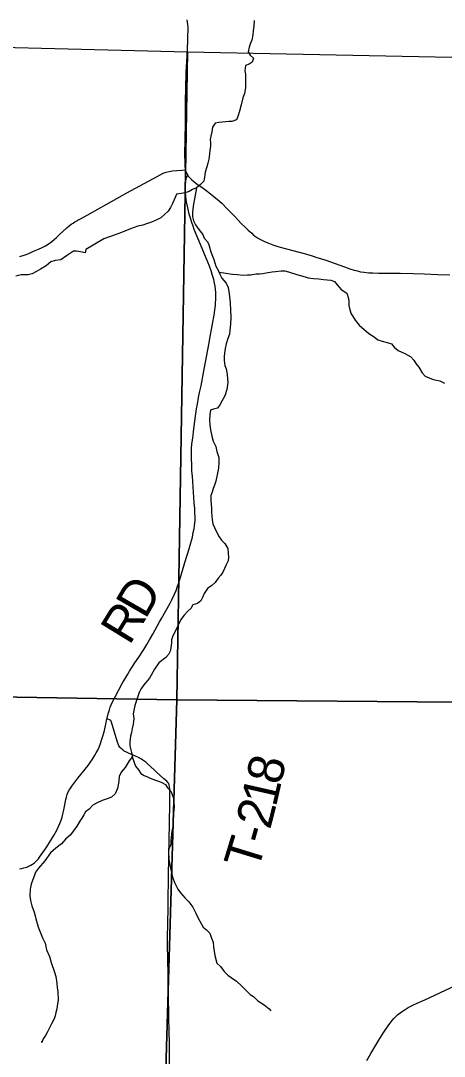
# Model space of a CAD drawing. Extents: x -1.2 to 34, y -8.5 to 22.
# Drawn here: x 7.031 to 7.701, y 15.11 to 16.749 of the extents above; entities that cross this region are included whole.
import ezdxf

# ---------------------------------------------------------------- set-up
doc = ezdxf.new("R2010")
doc.units = 0
for name, color, linetype in [('GM_X_County_Road', 7, 'Continuous'), ('GM_X_Minor_River', 7, 'Continuous'), ('GM_X_Section', 7, 'Continuous'), ('GM_X_Township_Road', 7, 'Continuous'), ('GM_X_Township_Road_Text', 7, 'Continuous')]:
    doc.layers.add(name, color=color, linetype=linetype)

msp = doc.modelspace()

# ---------------------------------------------------------------- linework, layer by layer
at = {"layer": 'GM_X_County_Road'}
for points in [[(7.2935, 16.7497), (7.2943, 16.746), (7.2948, 16.7425), (7.2951, 16.7383), (7.2953, 16.7327), (7.2949, 16.7256), (7.2946, 16.7165), (7.2934, 16.6928), (7.292, 16.6666), (7.2914, 16.6409), (7.2912, 16.6224), (7.291, 16.5891), (7.2905, 16.5581), (7.2902, 16.5394), (7.2905, 16.5216), (7.2907, 16.5172), (7.291, 16.514), (7.2913, 16.5128), (7.2916, 16.5112), (7.2925, 16.5088), (7.2938, 16.5061), (7.2951, 16.504), (7.2956, 16.5031), (7.2963, 16.5022), (7.2978, 16.5004), (7.2989, 16.4992), (7.3012, 16.497), (7.3047, 16.494), (7.3107, 16.4896), (7.3172, 16.4851), (7.3256, 16.4789), (7.3311, 16.4745), (7.3365, 16.4704), (7.3422, 16.4655), (7.3488, 16.4598), (7.3582, 16.4505), (7.3693, 16.4389), (7.3797, 16.4279), (7.3864, 16.4214), (7.3905, 16.4173), (7.3962, 16.4121), (7.3992, 16.4094), (7.4024, 16.4071), (7.4056, 16.4049), (7.4102, 16.4021), (7.4153, 16.3995), (7.4216, 16.3969), (7.4297, 16.394), (7.436, 16.392), (7.4411, 16.3904), (7.4813, 16.3794), (7.4866, 16.3779), (7.492, 16.3763), (7.499, 16.3741), (7.505, 16.3721), (7.5133, 16.3694), (7.5281, 16.3642), (7.5428, 16.3589), (7.5516, 16.3559), (7.5583, 16.3538), (7.5633, 16.3525), (7.5684, 16.3514), (7.574, 16.3505), (7.5811, 16.3498), (7.588, 16.3494), (7.5967, 16.3492), (7.6308, 16.3491), (7.6517, 16.3486), (7.6692, 16.3481), (7.6908, 16.3472), (7.7094, 16.3463)], [(7.5783, 15.1031), (7.5846, 15.1146), (7.5892, 15.1223), (7.5957, 15.1327), (7.6032, 15.1447), (7.6085, 15.153), (7.6149, 15.1619), (7.6185, 15.1666), (7.6211, 15.1696), (7.6241, 15.1727), (7.627, 15.1755), (7.631, 15.1788), (7.6345, 15.1814), (7.6389, 15.1841), (7.6438, 15.187), (7.6512, 15.1908), (7.658, 15.194), (7.6699, 15.1994), (7.7186, 15.2218)]]:
    msp.add_lwpolyline(points, dxfattribs=at)
at = {"layer": 'GM_X_Minor_River'}
for points in [[(7.4, 16.7488), (7.3997, 16.74), (7.3987, 16.7324), (7.398, 16.7259), (7.3963, 16.7179), (7.3941, 16.7129), (7.3923, 16.7064), (7.3905, 16.6991), (7.3936, 16.6938), (7.3989, 16.6893), (7.3971, 16.6828), (7.3923, 16.6797), (7.3862, 16.6777), (7.3852, 16.669), (7.3864, 16.664), (7.3862, 16.6545), (7.3864, 16.6423), (7.3846, 16.6335), (7.3824, 16.6267), (7.3796, 16.6152), (7.3767, 16.6056), (7.3741, 16.5972), (7.3723, 16.5915), (7.3648, 16.5891), (7.3599, 16.589), (7.355, 16.5886), (7.3444, 16.5873), (7.3383, 16.5864), (7.3343, 16.5799), (7.3332, 16.5726), (7.3318, 16.5657), (7.3308, 16.5604), (7.3312, 16.5555), (7.3309, 16.5494), (7.3302, 16.5436), (7.3296, 16.5375), (7.3286, 16.5295), (7.3271, 16.523), (7.3253, 16.5173), (7.3228, 16.5089), (7.3218, 16.5012), (7.3203, 16.4948), (7.3155, 16.4893), (7.3088, 16.4839), (7.3024, 16.4812), (7.2975, 16.4784), (7.2911, 16.4764), (7.2847, 16.4752), (7.2775, 16.4739), (7.2753, 16.469), (7.2709, 16.4594), (7.2679, 16.4532), (7.2639, 16.4471), (7.2523, 16.4366), (7.2474, 16.4339), (7.2376, 16.4296), (7.2297, 16.4272), (7.224, 16.4252), (7.2161, 16.4235), (7.2044, 16.4192), (7.1901, 16.4132), (7.1788, 16.4093), (7.1623, 16.4033), (7.1454, 16.3932), (7.1337, 16.3865), (7.1331, 16.3812), (7.1255, 16.383), (7.1194, 16.3836), (7.1145, 16.3836), (7.1032, 16.3765), (7.0946, 16.3703), (7.0855, 16.369), (7.0784, 16.367), (7.0713, 16.3608), (7.0623, 16.3554), (7.0548, 16.3511), (7.0491, 16.3479), (7.0427, 16.3463), (7.0366, 16.3466), (7.0314, 16.3462), (7.0234, 16.3441)], [(7.3088, 16.4839), (7.3056, 16.4667), (7.3042, 16.4583), (7.3032, 16.4511), (7.3025, 16.445), (7.3026, 16.4381), (7.3042, 16.4321), (7.3073, 16.4253), (7.3127, 16.4181), (7.3189, 16.4102), (7.3213, 16.4042), (7.3267, 16.3981), (7.329, 16.3925), (7.3314, 16.3826), (7.3342, 16.3758), (7.3361, 16.3705), (7.3393, 16.3599), (7.3436, 16.3527), (7.3456, 16.3474), (7.3491, 16.341), (7.3556, 16.3331), (7.3591, 16.3263), (7.3608, 16.3164), (7.3621, 16.3023), (7.3627, 16.2906), (7.3632, 16.2795), (7.3626, 16.2685), (7.3616, 16.2589), (7.3609, 16.2525), (7.3584, 16.2459), (7.3559, 16.2372), (7.3541, 16.2299), (7.3534, 16.2223), (7.3528, 16.2166), (7.3528, 16.2108), (7.3537, 16.2029), (7.3557, 16.1976), (7.3573, 16.1888), (7.3582, 16.1816), (7.3583, 16.1759), (7.3569, 16.1648), (7.354, 16.1549), (7.3492, 16.1464), (7.3459, 16.1407), (7.3422, 16.1357), (7.3358, 16.1337), (7.3309, 16.1321), (7.3302, 16.1256), (7.3296, 16.1165), (7.3301, 16.1092), (7.3313, 16.1009), (7.3334, 16.0914), (7.3354, 16.083), (7.3393, 16.0747), (7.3413, 16.0668), (7.3441, 16.0573), (7.3442, 16.0501), (7.3436, 16.0405), (7.3415, 16.0302), (7.3397, 16.0199), (7.3375, 16.0138), (7.3353, 16.0084), (7.3335, 16.0023), (7.3317, 15.9973), (7.3314, 15.9897), (7.3319, 15.9829), (7.3328, 15.9772), (7.3328, 15.9711), (7.3333, 15.9646), (7.3338, 15.9593), (7.335, 15.9525), (7.3374, 15.9464), (7.3405, 15.9396), (7.3448, 15.9321), (7.3486, 15.9268), (7.354, 15.9211), (7.3583, 15.9132), (7.3592, 15.906), (7.3596, 15.8999), (7.359, 15.8938), (7.356, 15.8877), (7.3534, 15.8819), (7.3505, 15.8762), (7.3475, 15.8712), (7.3431, 15.8662), (7.3386, 15.8596), (7.333, 15.8546), (7.3263, 15.8503), (7.3211, 15.8422), (7.3185, 15.8361), (7.3156, 15.8304), (7.3107, 15.8265), (7.3032, 15.8241), (7.3002, 15.8187), (7.295, 15.8141), (7.2894, 15.8079), (7.2842, 15.8013), (7.275, 15.7822), (7.2713, 15.7753), (7.2695, 15.7691), (7.2696, 15.7642)], [(7.3444, 16.3506), (7.3524, 16.3494), (7.3584, 16.3484), (7.366, 16.3477), (7.374, 16.3467), (7.3827, 16.3457), (7.3895, 16.3462), (7.3944, 16.3466), (7.4031, 16.3479), (7.4088, 16.348), (7.4137, 16.3484), (7.419, 16.3496), (7.4288, 16.3513), (7.4341, 16.3518), (7.4428, 16.3527), (7.4488, 16.3528), (7.4542, 16.3509), (7.4694, 16.3466), (7.4808, 16.343), (7.4857, 16.3419), (7.4941, 16.3405), (7.5024, 16.3402), (7.5096, 16.3392), (7.5214, 16.3378), (7.5271, 16.3357), (7.5313, 16.3304), (7.5379, 16.3232), (7.5467, 16.3173), (7.5494, 16.309), (7.5499, 16.304), (7.55, 16.2979), (7.5508, 16.293), (7.5528, 16.2858), (7.5598, 16.2748), (7.5663, 16.2666), (7.5813, 16.2535), (7.5897, 16.2483), (7.5958, 16.2438), (7.6027, 16.2412), (7.6103, 16.2391), (7.6171, 16.2373), (7.6217, 16.232), (7.6279, 16.2268), (7.6385, 16.222), (7.6477, 16.2168), (7.6527, 16.2115), (7.6558, 16.2062), (7.6608, 16.2002), (7.6658, 16.1915), (7.6705, 16.1859), (7.683, 16.1808), (7.6887, 16.1797), (7.6937, 16.1786), (7.7009, 16.1749)], [(7.2696, 15.7642), (7.2682, 15.7562), (7.2671, 15.7508), (7.2649, 15.7459), (7.2605, 15.7408), (7.2496, 15.7323), (7.2426, 15.7223), (7.2374, 15.7131), (7.2344, 15.7081), (7.2255, 15.6977), (7.2207, 15.6908), (7.2181, 15.6854), (7.2156, 15.6777), (7.2112, 15.6651), (7.2105, 15.6598), (7.2088, 15.6518), (7.2096, 15.6442), (7.209, 15.6354), (7.2072, 15.6285), (7.2062, 15.622), (7.2044, 15.6163), (7.2033, 15.6075), (7.2034, 15.6014), (7.2062, 15.5908), (7.2079, 15.5821), (7.2126, 15.5688), (7.2172, 15.5632), (7.2207, 15.5575), (7.2261, 15.5542), (7.2326, 15.5516), (7.2383, 15.5487), (7.2531, 15.5439), (7.26, 15.5398), (7.2631, 15.5349), (7.2681, 15.5293), (7.2704, 15.5244), (7.2724, 15.5183), (7.2737, 15.5046), (7.2728, 15.494), (7.2718, 15.4806), (7.2719, 15.4753), (7.2701, 15.4661), (7.2685, 15.4513), (7.2682, 15.4448), (7.2652, 15.4383), (7.2649, 15.4333), (7.2651, 15.4212), (7.2675, 15.4102), (7.2696, 15.401), (7.2712, 15.3935), (7.2747, 15.384), (7.2794, 15.3742), (7.2837, 15.3685), (7.291, 15.3599), (7.2968, 15.3543), (7.3033, 15.346), (7.3076, 15.3373), (7.3115, 15.3286), (7.3197, 15.3142), (7.3247, 15.3101), (7.33, 15.3049), (7.3328, 15.2969), (7.3352, 15.2905), (7.336, 15.2829), (7.3369, 15.2764), (7.3381, 15.2696), (7.3409, 15.2575), (7.3467, 15.2518), (7.3525, 15.2439), (7.3586, 15.2383), (7.3636, 15.2346), (7.3724, 15.2286), (7.3805, 15.2207), (7.3882, 15.2136), (7.3939, 15.2076), (7.3993, 15.2043), (7.4058, 15.1979), (7.4161, 15.1912), (7.4238, 15.1849), (7.4264, 15.1817)], [(7.2075, 15.5841), (7.2027, 15.5774), (7.1993, 15.5721), (7.196, 15.5671), (7.1897, 15.5594), (7.1867, 15.5528), (7.1861, 15.546), (7.185, 15.5391), (7.184, 15.5334), (7.1803, 15.5253), (7.1743, 15.5199), (7.1679, 15.5172), (7.1596, 15.5148), (7.1518, 15.5108), (7.145, 15.5073), (7.139, 15.5011), (7.1334, 15.4969), (7.1308, 15.4919), (7.1275, 15.4869), (7.1245, 15.4819), (7.1197, 15.4742), (7.1145, 15.4665), (7.109, 15.4599), (7.1022, 15.4538), (7.0955, 15.446), (7.0865, 15.4391), (7.0779, 15.4321), (7.069, 15.4194), (7.059, 15.4074), (7.0542, 15.4013), (7.0524, 15.3952), (7.0494, 15.3879), (7.0476, 15.3825), (7.0458, 15.3745), (7.0452, 15.3638), (7.0465, 15.3566), (7.0485, 15.3479), (7.052, 15.3381), (7.0536, 15.3324), (7.0549, 15.3274), (7.0568, 15.3202), (7.0588, 15.3134), (7.062, 15.3051), (7.0655, 15.2972), (7.0694, 15.2888), (7.0718, 15.2786), (7.0765, 15.268), (7.079, 15.2581), (7.0845, 15.243), (7.0865, 15.2362), (7.0878, 15.2255), (7.0886, 15.2183), (7.0898, 15.2122), (7.09, 15.1989), (7.089, 15.1928), (7.088, 15.1848), (7.0865, 15.1791), (7.0855, 15.1741), (7.0837, 15.1691), (7.0796, 15.1611), (7.0759, 15.1538), (7.0734, 15.1484), (7.07, 15.1427), (7.0663, 15.1373), (7.0641, 15.1319), (7.0645, 15.1338)]]:
    msp.add_lwpolyline(points, dxfattribs=at)
at = {"layer": 'GM_X_Section'}
msp.add_lwpolyline([(6.7905, 16.7121), (7.2949, 16.6991), (7.2776, 15.674), (6.2657, 15.6908), (6.2717, 16.2314)], dxfattribs=at)
for points in [[(7.2949, 16.6991), (8.3136, 16.6787), (8.2912, 15.6653), (7.2776, 15.674)], [(7.2776, 15.674), (7.2479, 14.6639), (6.2441, 14.6736), (6.2657, 15.6908)], [(8.2912, 15.6653), (8.2689, 14.6439), (7.2479, 14.6639), (7.2776, 15.674)]]:
    msp.add_lwpolyline(points, close=True, dxfattribs=at)
at = {"layer": 'GM_X_Township_Road'}
for points in [[(7.0289, 15.4064), (7.032, 15.407), (7.0361, 15.408), (7.0405, 15.4094), (7.0438, 15.4106), (7.0472, 15.4124), (7.0496, 15.414), (7.0525, 15.4163), (7.0554, 15.4189), (7.0588, 15.4226), (7.0609, 15.4251), (7.0686, 15.4359), (7.0722, 15.4413), (7.0779, 15.4508), (7.0831, 15.4595), (7.0878, 15.4679), (7.09, 15.4723), (7.0927, 15.4784), (7.0947, 15.4834), (7.0963, 15.4884), (7.0975, 15.4928), (7.0985, 15.4972), (7.1, 15.5051), (7.1024, 15.516), (7.1032, 15.5201), (7.1044, 15.5239), (7.1057, 15.5272), (7.1076, 15.5312), (7.11, 15.5349), (7.1118, 15.5374), (7.1214, 15.55), (7.1374, 15.57), (7.1409, 15.5749), (7.1445, 15.5802), (7.1474, 15.5852), (7.1503, 15.5901), (7.1527, 15.5944), (7.1548, 15.599), (7.1572, 15.605), (7.1594, 15.6117), (7.1614, 15.6183), (7.1632, 15.6252), (7.1654, 15.6353), (7.1672, 15.6437), (7.1675, 15.645), (7.1694, 15.652), (7.1711, 15.6579), (7.1725, 15.6621), (7.1741, 15.666), (7.1778, 15.6741), (7.1801, 15.6787), (7.1914, 15.6998), (7.1939, 15.7042), (7.2001, 15.7145), (7.2029, 15.7191), (7.2115, 15.7327), (7.2178, 15.7415), (7.2259, 15.7538), (7.2305, 15.7613), (7.2348, 15.7687), (7.24, 15.7781), (7.2505, 15.7973), (7.2536, 15.8026), (7.2672, 15.8268), (7.2701, 15.8322), (7.2743, 15.8413), (7.2766, 15.847), (7.2786, 15.8523), (7.2809, 15.8592), (7.2892, 15.8874), (7.2904, 15.891), (7.2973, 15.9127), (7.299, 15.9185), (7.3024, 15.9315), (7.3039, 15.9385), (7.305, 15.9443), (7.3058, 15.95), (7.3066, 15.9575), (7.3068, 15.9632), (7.3065, 15.9697), (7.3061, 15.9768), (7.3055, 15.9854), (7.3024, 16.0277), (7.3018, 16.036), (7.3013, 16.0457), (7.3009, 16.0556), (7.3012, 16.0711), (7.3018, 16.0791), (7.3029, 16.0881), (7.3047, 16.1028), (7.3063, 16.1151), (7.3091, 16.1343), (7.3104, 16.1419), (7.3122, 16.1521), (7.3138, 16.16), (7.3162, 16.1709), (7.3212, 16.1974), (7.3289, 16.2388), (7.3301, 16.2457), (7.3372, 16.286), (7.338, 16.2914), (7.3388, 16.2973), (7.3391, 16.3014), (7.3396, 16.3077), (7.3397, 16.3131), (7.3396, 16.3179), (7.3391, 16.3235), (7.3383, 16.3286), (7.3375, 16.3332), (7.3362, 16.339), (7.3345, 16.3452), (7.3322, 16.3527), (7.3296, 16.3599), (7.327, 16.3665), (7.3155, 16.3944), (7.3054, 16.4182), (7.3035, 16.4232), (7.3013, 16.4292), (7.2992, 16.4359), (7.2975, 16.4422), (7.2963, 16.4476), (7.2933, 16.462), (7.2922, 16.4701), (7.2914, 16.4779), (7.291, 16.4844), (7.2912, 16.4921), (7.2917, 16.495), (7.2924, 16.498), (7.2933, 16.5005), (7.2941, 16.5021), (7.2951, 16.504)], [(7.0298, 16.3753), (7.0381, 16.3783), (7.0437, 16.3804), (7.0514, 16.3836), (7.059, 16.3868), (7.065, 16.3896), (7.0701, 16.3924), (7.0746, 16.3952), (7.0798, 16.3987), (7.0839, 16.4023), (7.0877, 16.4056), (7.092, 16.4098), (7.1041, 16.4209), (7.1078, 16.4241), (7.1107, 16.4264), (7.1137, 16.4284), (7.1163, 16.4301), (7.1255, 16.4352), (7.1359, 16.4408), (7.1829, 16.4673), (7.199, 16.4763), (7.2467, 16.5022), (7.2563, 16.5071), (7.261, 16.5088), (7.2657, 16.51), (7.2711, 16.511), (7.278, 16.5115), (7.2858, 16.5121), (7.2913, 16.5128)], [(7.2663, 15.0449), (7.2661, 15.1342), (7.2658, 15.1455), (7.2655, 15.155), (7.2654, 15.1656), (7.2651, 15.1838), (7.265, 15.1873), (7.2649, 15.1925), (7.2648, 15.1958), (7.2646, 15.2004), (7.2645, 15.2051), (7.2643, 15.2114), (7.2642, 15.2199), (7.2641, 15.2306), (7.264, 15.2387), (7.2635, 15.2645), (7.2631, 15.2853), (7.2633, 15.3044), (7.2635, 15.3138), (7.2637, 15.3233), (7.2638, 15.3283), (7.2639, 15.3364), (7.2643, 15.3703), (7.2644, 15.3785), (7.2649, 15.4049), (7.2651, 15.4142), (7.2653, 15.4317), (7.2655, 15.4477), (7.2663, 15.4832), (7.267, 15.5059), (7.2668, 15.5318), (7.2667, 15.5329), (7.2657, 15.5392), (7.2654, 15.5403), (7.2645, 15.5421), (7.2638, 15.5432), (7.2618, 15.5453), (7.2574, 15.549), (7.2452, 15.5598), (7.2424, 15.5624), (7.2303, 15.5738), (7.2287, 15.5751), (7.2241, 15.5786), (7.2219, 15.5799), (7.2174, 15.5825), (7.2124, 15.585), (7.2062, 15.5876), (7.2006, 15.5899), (7.1983, 15.5909), (7.1948, 15.5929), (7.1924, 15.5947), (7.1896, 15.5971), (7.1882, 15.5985), (7.1863, 15.6012), (7.1857, 15.6025), (7.1836, 15.6087), (7.1743, 15.6388), (7.1738, 15.64), (7.1732, 15.641), (7.1725, 15.6416), (7.1714, 15.6421), (7.1685, 15.6432), (7.1672, 15.6437)]]:
    msp.add_lwpolyline(points, dxfattribs=at)

# ---------------------------------------------------------------- texts
at = {"layer": 'GM_X_Township_Road_Text'}
for s, rotation, p in [('D', 60.0324, (7.228, 15.8001)), ('R', 58.4505, (7.2028, 15.7589)), ('8', 77.7505, (7.4423, 15.5378)), ('1', 77.1601, (7.4344, 15.503)), ('2', 75.6437, (7.4253, 15.4675)), ('-', 74.1568, (7.4185, 15.4435)), ('T', 72.9366, (7.4057, 15.4016))]:
    msp.add_text(s, height=0.0568, rotation=rotation, dxfattribs=at).set_placement(p)

doc.saveas('drawing.dxf')
